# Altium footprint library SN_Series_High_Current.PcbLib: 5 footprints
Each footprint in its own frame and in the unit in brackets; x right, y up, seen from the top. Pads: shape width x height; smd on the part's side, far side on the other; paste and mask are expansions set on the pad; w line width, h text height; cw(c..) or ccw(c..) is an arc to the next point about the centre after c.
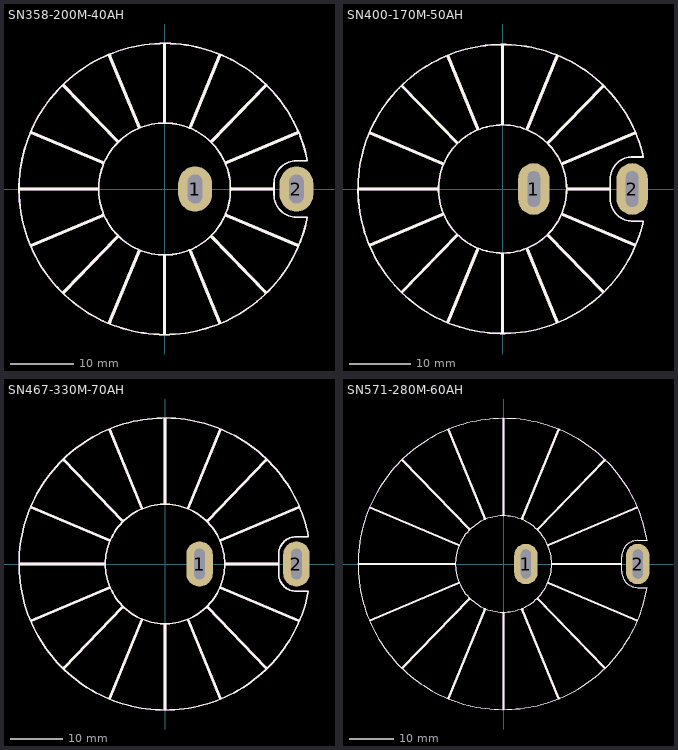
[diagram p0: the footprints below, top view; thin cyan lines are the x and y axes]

## PCBComponent_1 [mil]

## SN358-200M-40AH [mil]
pads (2):
  oval 210x280 hole 180 slot 90 at 0 deg: 1(190,0) 2(820,0)
Top Overlay:
  circle w10: c0,0 r410
  lines w10: -898.39,-109.15 cw(c0,0) 887.86,175.29 ; -898.31,-109.86 ccw(c0,0) 887.87,-175.27 ; 887.87,-175 820,-175 cw(c820,-35) 680,-35 680,35 cw(c820,35) 820,175 887.86,175
  lines w19.68: -900,0 -415,0 ; -829.39,-351.44 -385.67,-163.42 ; -829.39,351.44 -385.67,163.42 ; -627.17,-642.75 -292.52,-297.56 ; -627.17,642.75 -292.52,297.56 ; -341.12,-829.54 -160.12,-387.9 ; -341.12,829.54 -160.12,387.9 ; 0,-900 0,-415 ; 0,415 0,900 ; 160.12,-387.9 341.12,-829.54 ; 160.12,387.9 341.12,829.54 ; 292.52,-297.56 627.17,-642.75 ; 292.52,297.56 627.17,642.75 ; 385.67,-163.42 829.39,-351.44 ; 385.67,163.42 829.39,351.44 ; 420,0 670,0
Mechanical 29:
  circle w10: c0,0 r410
  lines w10: -898.39,-109.15 cw(c0,0) 887.86,175.29 ; -898.31,-109.86 ccw(c0,0) 887.87,-175.27 ; 887.87,-175 820,-175 cw(c820,-35) 680,-35 680,35 cw(c820,35) 820,175 887.86,175
  lines w19.68: -900,0 -415,0 ; -829.39,-351.44 -385.67,-163.42 ; -829.39,351.44 -385.67,163.42 ; -627.17,-642.75 -292.52,-297.56 ; -627.17,642.75 -292.52,297.56 ; -341.12,-829.54 -160.12,-387.9 ; -341.12,829.54 -160.12,387.9 ; 0,-900 0,-415 ; 0,415 0,900 ; 160.12,-387.9 341.12,-829.54 ; 160.12,387.9 341.12,829.54 ; 292.52,-297.56 627.17,-642.75 ; 292.52,297.56 627.17,642.75 ; 385.67,-163.42 829.39,-351.44 ; 385.67,163.42 829.39,351.44 ; 420,0 670,0
  text "'.Designator'" at -290,145.15 h400

## SN400-170M-50AH [mil]
pads (2):
  oval 200x330 hole 230 slot 80 at 0 deg: 1(200,0) 2(830,0)
Top Overlay:
  circle w10: c0,0 r410
  lines w10: -918.25,-111.56 cw(c0,0) 901.99,205.05 ; -918.16,-112.28 ccw(c0,0) 901.8,-205.87 ; 825,-205 901.8,-205 ; 825,205 901.77,205 ; 830,-205 cw(c830,-65) 690,-65 690,65 cw(c830,65) 830,205
  lines w19.68: -920,0 -415,0 ; -846.05,-358.49 -385.67,-163.42 ; -846.05,358.49 -385.67,163.42 ; -640.55,-656.55 -292.52,-297.56 ; -640.55,656.55 -292.52,297.56 ; -349.74,-850.55 -160.12,-387.9 ; -349.74,850.55 -160.12,387.9 ; 0,-915 0,-415 ; 0,415 0,915 ; 160.12,-387.9 349.74,-850.55 ; 160.12,387.9 349.74,850.55 ; 292.52,-297.56 640.55,-656.55 ; 292.52,297.56 640.55,656.55 ; 385.67,-163.42 846.05,-358.49 ; 385.67,163.42 846.05,358.49 ; 420,0 685,0
Mechanical 29:
  circle w10: c0,0 r410
  lines w10: -918.25,-111.56 cw(c0,0) 901.99,205.05 ; -918.16,-112.28 ccw(c0,0) 901.8,-205.87 ; 825,-205 901.8,-205 ; 825,205 901.77,205 ; 830,-205 cw(c830,-65) 690,-65 690,65 cw(c830,65) 830,205
  lines w19.68: -920,0 -415,0 ; -846.05,-358.49 -385.67,-163.42 ; -846.05,358.49 -385.67,163.42 ; -640.55,-656.55 -292.52,-297.56 ; -640.55,656.55 -292.52,297.56 ; -349.74,-850.55 -160.12,-387.9 ; -349.74,850.55 -160.12,387.9 ; 0,-915 0,-415 ; 0,415 0,915 ; 160.12,-387.9 349.74,-850.55 ; 160.12,387.9 349.74,850.55 ; 292.52,-297.56 640.55,-656.55 ; 292.52,297.56 640.55,656.55 ; 385.67,-163.42 846.05,-358.49 ; 385.67,163.42 846.05,358.49 ; 420,0 685,0
  text "'.Designator'" at -290,145.15 h400

## SN467-330M-70AH [mil]
pads (2):
  oval 200x340 hole 230 slot 80 at 0 deg: 1(260,0) 2(990,0)
Top Overlay:
  circle w10: c0,0 r450
  lines w10: -1091.97,-132.67 cw(c0,0) 1080.69,205.19 ; -1091.87,-133.53 ccw(c0,0) 1080.69,-205.2 ; 1080.69,-205 990,-205 cw(c990,-70) 855,-70 855,70 cw(c990,70) 990,205 1080.69,205
  lines w19.68: -1090,0 -455,0 ; -1008.58,-427.37 -418.93,-177.51 ; -1008.58,427.37 -418.93,177.51 ; -762.43,-782.27 -319.55,-325.44 ; -762.43,782.27 -319.55,325.44 ; -415.66,-1011.39 -174.25,-422.36 ; -415.66,1011.39 -174.25,422.36 ; 0,-1090 0,-455 ; 0,455 0,1090 ; 174.25,-422.36 415.66,-1011.39 ; 174.25,422.36 415.66,1011.39 ; 319.55,-325.44 762.43,-782.27 ; 319.55,325.44 762.43,782.27 ; 418.93,-177.51 1008.58,-427.37 ; 418.93,177.51 1008.58,427.37 ; 455,0 845,0
Mechanical 29:
  circle w10: c0,0 r450
  lines w10: -1091.97,-132.67 cw(c0,0) 1080.69,205.19 ; -1091.87,-133.53 ccw(c0,0) 1080.69,-205.2 ; 1080.69,-205 990,-205 cw(c990,-70) 855,-70 855,70 cw(c990,70) 990,205 1080.69,205
  lines w19.68: -1090,0 -455,0 ; -1008.58,-427.37 -418.93,-177.51 ; -1008.58,427.37 -418.93,177.51 ; -762.43,-782.27 -319.55,-325.44 ; -762.43,782.27 -319.55,325.44 ; -415.66,-1011.39 -174.25,-422.36 ; -415.66,1011.39 -174.25,422.36 ; 0,-1090 0,-455 ; 0,455 0,1090 ; 174.25,-422.36 415.66,-1011.39 ; 174.25,422.36 415.66,1011.39 ; 319.55,-325.44 762.43,-782.27 ; 319.55,325.44 762.43,782.27 ; 418.93,-177.51 1008.58,-427.37 ; 418.93,177.51 1008.58,427.37 ; 455,0 845,0
  text "'.Designator'" at -290,145.15 h400

## SN571-280M-60AH [mil]
pads (2):
  oval 210x360 hole 260 slot 90 at 0 deg: 1(200,0) 2(1200,0)
Top Overlay:
  circle w10: c0,0 r430
  lines w10: -1290.51,-156.79 cw(c0,0) 1282.9,210.13 ; -1290.39,-157.8 ccw(c0,0) 1282.9,-210.15 ; 1282.9,-210 1200,-210 cw(c1200,-65) 1055,-65 1055,65 cw(c1200,65) 1200,210 1282.9,210
  lines w19.68: -1295,0 -435,0 ; -1192.37,-505.24 -401.98,-170.33 ; -1192.37,505.24 -401.98,170.33 ; -904.24,-928.54 -304.78,-310.21 ; -904.24,928.54 -304.78,310.21 ; -492.8,-1199.61 -166.82,-404.25 ; -492.8,1199.61 -166.82,404.25 ; 0,-1295 0,-435 ; 0,435 0,1295 ; 166.82,-404.25 492.8,-1199.61 ; 166.82,404.25 492.8,1199.61 ; 304.78,-310.21 904.24,-928.54 ; 304.78,310.21 904.24,928.54 ; 401.98,-170.33 1192.37,-505.24 ; 401.98,170.33 1192.37,505.24 ; 440,0 1045,0
Mechanical 29:
  circle w10: c0,0 r430
  lines w10: -1290.51,-156.79 cw(c0,0) 1282.9,210.13 ; -1290.39,-157.8 ccw(c0,0) 1282.9,-210.15 ; 1282.9,-210 1200,-210 cw(c1200,-65) 1055,-65 1055,65 cw(c1200,65) 1200,210 1282.9,210
  lines w19.68: -1295,0 -435,0 ; -1192.37,-505.24 -401.98,-170.33 ; -1192.37,505.24 -401.98,170.33 ; -904.24,-928.54 -304.78,-310.21 ; -904.24,928.54 -304.78,310.21 ; -492.8,-1199.61 -166.82,-404.25 ; -492.8,1199.61 -166.82,404.25 ; 0,-1295 0,-435 ; 0,435 0,1295 ; 166.82,-404.25 492.8,-1199.61 ; 166.82,404.25 492.8,1199.61 ; 304.78,-310.21 904.24,-928.54 ; 304.78,310.21 904.24,928.54 ; 401.98,-170.33 1192.37,-505.24 ; 401.98,170.33 1192.37,505.24 ; 440,0 1045,0
  text "'.Designator'" at -290,145.15 h400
